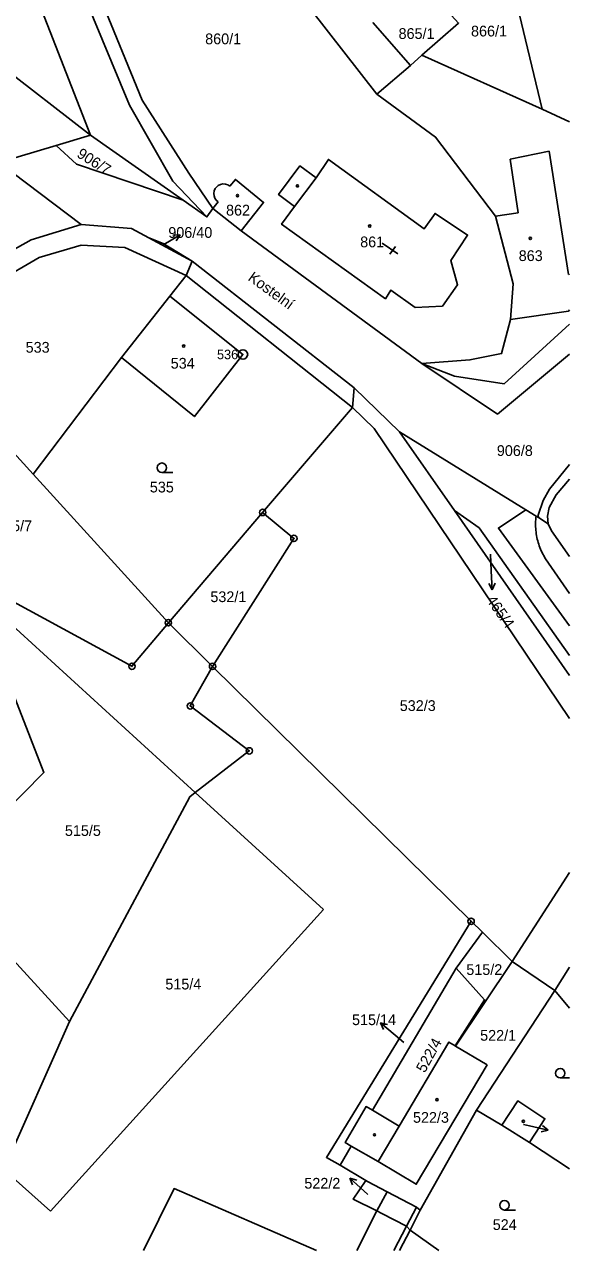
# Model space of a CAD drawing. Extents: x -776606 to -776076, y -974328 to -973875.
# Drawn here: x -776161.7 to -776075.5, y -974327.7 to -974133.7 of the extents above; entities that cross this region are included whole.
import ezdxf

# ---------------------------------------------------------------- set-up
doc = ezdxf.new("R2010")
doc.units = 0
for name, color, linetype in [('Hranice parcel', 7, 'Continuous'), ('Parcelní čísla', 7, 'Continuous'), ('Pop  PČ popisy', 7, 'Continuous'), ('Vnitřní kresba', 7, 'Continuous'), ('Značky bodu BP', 7, 'Continuous'), ('Značky budov', 7, 'Continuous'), ('Značky kultur', 7, 'Continuous')]:
    doc.layers.add(name, color=color, linetype=linetype)

msp = doc.modelspace()

# ---------------------------------------------------------------- linework, layer by layer
at = {"layer": 'Hranice parcel'}
for p, q in [((-776079.84, -974147.11), (-776087.39, -974115.46)), ((-776151.23, -974151.21), (-776174.9, -974132.93)), ((-776079.84, -974147.11), (-776098.85, -974138.57)), ((-776075.52, -974149.12), (-776079.84, -974147.11)), ((-776156.67, -974152.84), (-776151.23, -974151.21)), ((-776136.62, -974161.48), (-776151.23, -974151.21)), ((-776165.74, -974155.55), (-776156.67, -974152.84)), ((-776165.74, -974155.55), (-776152.75, -974165.36)), ((-776131.07, -974161.76), (-776131.92, -974162.82)), ((-776131.92, -974162.82), (-776127.42, -974166.36)), ((-776142.03, -974167.44), (-776139.75, -974168.37)), ((-776135.17, -974171.14), (-776142.03, -974167.44)), ((-776098.84, -974187.33), (-776127.42, -974166.36)), ((-776139.75, -974168.37), (-776135.17, -974171.14)), ((-776109.57, -974191.21), (-776135.17, -974171.14)), ((-776146.33, -974186.41), (-776138.73, -974176.69)), ((-776160.31, -974204.85), (-776146.33, -974186.41)), ((-776086.91, -974195.36), (-776075.52, -974185.86)), ((-776098.84, -974187.33), (-776086.91, -974195.36)), ((-776102.37, -974198.16), (-776109.57, -974191.21)), ((-776102.37, -974198.16), (-776093.72, -974210.57)), ((-776082.42, -974210.48), (-776102.37, -974198.16)), ((-776160.31, -974204.85), (-776138.94, -974228.35)), ((-776138.94, -974228.35), (-776124.04, -974210.91)), ((-776093.72, -974210.57), (-776075.52, -974236.68)), ((-776078.86, -974212.68), (-776080.43, -974211.71)), ((-776138.94, -974228.35), (-776144.7, -974235.24)), ((-776131.96, -974235.26), (-776138.94, -974228.35)), ((-776091.07, -974275.58), (-776131.96, -974235.26)), ((-776091.07, -974275.58), (-776089.29, -974277.33)), ((-776089.29, -974277.33), (-776093.45, -974283.01)), ((-776084.59, -974281.96), (-776089.29, -974277.33)), ((-776093.52, -974295.32), (-776084.59, -974281.96)), ((-776077.85, -974286.53), (-776084.59, -974281.96)), ((-776106.68, -974305.49), (-776093.45, -974283.01)), ((-776090.23, -974305.46), (-776077.85, -974286.53)), ((-776077.85, -974286.53), (-776075.52, -974289.31)), ((-776093.61, -974295.27), (-776093.52, -974295.32)), ((-776093.52, -974295.32), (-776088.52, -974298.29)), ((-776099.1, -974321.26), (-776090.23, -974305.46)), ((-776086.2, -974307.85), (-776090.23, -974305.46)), ((-776081.86, -974310.6), (-776086.2, -974307.85)), ((-776110.02, -974311.15), (-776111.8, -974314.18)), ((-776075.52, -974314.73), (-776081.86, -974310.6)), ((-776111.8, -974314.18), (-776107.73, -974316.58)), ((-776107.73, -974316.58), (-776107.43, -974316.76)), ((-776106, -974321.4), (-776109.16, -974327.66)), ((-776100.73, -974324.46), (-776099.1, -974321.26)), ((-776100.73, -974324.46), (-776102.39, -974327.66)), ((-776100.73, -974324.46), (-776101.29, -974323.83))]:
    msp.add_line(p, q, dxfattribs=at)
for points in [[(-776121.33, -974125.02), (-776116.42, -974131.34), (-776106, -974144.74)], [(-776098.85, -974138.57), (-776093.06, -974133.49), (-776098.09, -974127.94)], [(-776098.85, -974138.57), (-776100.67, -974140.17), (-776106, -974144.74)], [(-776106, -974144.74), (-776096.69, -974151.51), (-776087.2, -974164.02), (-776084.4, -974174.72), (-776084.85, -974180.38)], [(-776156.67, -974152.84), (-776153.49, -974155.81), (-776136.62, -974161.48)], [(-776118.97, -974162.5), (-776121.05, -974165.3), (-776104.61, -974177.1), (-776103.75, -974175.72), (-776099.89, -974178.5), (-776095.6, -974178.28), (-776093.22, -974174.87), (-776094.3, -974171.05), (-776091.62, -974167.01), (-776096.76, -974163.6), (-776098.49, -974166.02), (-776113.62, -974155.05), (-776115.59, -974157.96), (-776118.13, -974156.07), (-776121.51, -974160.61), (-776118.97, -974162.5)], [(-776129.22, -974159.3), (-776129.55, -974159.09), (-776129.92, -974158.97), (-776130.32, -974158.94), (-776130.7, -974159.02), (-776131.05, -974159.19), (-776131.27, -974159.37), (-776131.52, -974159.67), (-776131.68, -974160.03), (-776131.75, -974160.42), (-776131.72, -974160.81), (-776131.58, -974161.18), (-776131.36, -974161.5), (-776131.07, -974161.76)], [(-776127.42, -974166.36), (-776123.89, -974161.86), (-776128.33, -974158.21), (-776129.22, -974159.3)], [(-776131.92, -974162.82), (-776132.84, -974164.14), (-776136.62, -974161.48)], [(-776152.75, -974165.36), (-776160.65, -974167.77), (-776179.49, -974178.31), (-776182.59, -974180.14)], [(-776142.03, -974167.44), (-776144.77, -974165.96), (-776152.75, -974165.36)], [(-776138.73, -974176.69), (-776136.12, -974173.44), (-776135.17, -974171.14)], [(-776146.33, -974186.41), (-776134.81, -974195.73), (-776127.15, -974185.91), (-776138.73, -974176.69)], [(-776084.85, -974180.38), (-776075.69, -974179.07), (-776075.52, -974178.9)], [(-776182.59, -974180.14), (-776181.18, -974181.75), (-776178.4, -974184.94), (-776160.31, -974204.85)], [(-776084.85, -974180.38), (-776086.26, -974185.77), (-776091.27, -974186.78), (-776098.84, -974187.33)], [(-776098.84, -974187.33), (-776093.72, -974189.36), (-776085.86, -974190.55), (-776075.52, -974181.11)], [(-776187.91, -974186.49), (-776189.94, -974190.42), (-776197.63, -974205.37), (-776203.53, -974219.04), (-776202.03, -974219.5), (-776167.14, -974230.3), (-776158.63, -974252.03), (-776175.21, -974268.87), (-776154.58, -974291.43)], [(-776144.7, -974235.24), (-776164.02, -974224.74), (-776186.48, -974188.78), (-776187.91, -974186.49)], [(-776124.04, -974210.91), (-776109.85, -974194.3), (-776109.57, -974191.21)], [(-776080.43, -974211.71), (-776080.44, -974211.32), (-776079.69, -974209), (-776078.68, -974207.23), (-776075.52, -974203.34)], [(-776075.52, -974205.65), (-776077.62, -974208.13), (-776078.72, -974210.13), (-776078.98, -974211.47), (-776078.86, -974212.68)], [(-776075.52, -974228.83), (-776086.75, -974213.37), (-776082.42, -974210.48)], [(-776080.43, -974211.71), (-776080.8, -974211.48), (-776082.42, -974210.48)], [(-776124.04, -974210.91), (-776119.09, -974215), (-776131.96, -974235.26)], [(-776093.72, -974210.57), (-776089.82, -974213.33), (-776075.52, -974233.56)], [(-776078.86, -974212.68), (-776078.38, -974213.82), (-776075.52, -974217.88)], [(-776131.96, -974235.26), (-776135.48, -974241.52), (-776126.15, -974248.62), (-776134.68, -974255.2), (-776135.57, -974255.89), (-776154.58, -974291.43)], [(-776075.52, -974267.85), (-776084.59, -974281.96)], [(-776111.8, -974314.18), (-776113.96, -974312.94), (-776091.07, -974275.58)], [(-776093.45, -974283.01), (-776088.93, -974288), (-776093.61, -974295.27)], [(-776075.52, -974282.82), (-776077.85, -974286.53)], [(-776154.58, -974291.43), (-776164.96, -974314.87), (-776168.27, -974322.35)], [(-776093.61, -974295.27), (-776094.59, -974294.69), (-776102.46, -974307.99), (-776106.68, -974305.49)], [(-776088.52, -974298.29), (-776099.73, -974317.18), (-776105.78, -974313.61), (-776110.02, -974311.15)], [(-776110.02, -974311.15), (-776111, -974310.58), (-776107.67, -974304.9), (-776106.68, -974305.49)], [(-776081.86, -974310.6), (-776081.78, -974310.48), (-776079.41, -974306.81), (-776083.7, -974304), (-776086.2, -974307.85)], [(-776107.73, -974316.58), (-776109.71, -974319.55), (-776106, -974321.4)], [(-776107.43, -974316.76), (-776104.34, -974318.39), (-776099.72, -974320.81), (-776099.1, -974321.26)], [(-776115.51, -974327.66), (-776138.03, -974317.86), (-776142.89, -974327.66)], [(-776101.29, -974323.83), (-776105.17, -974321.83), (-776106, -974321.4)], [(-776101.29, -974323.83), (-776103.28, -974327.66)], [(-776096.18, -974327.66), (-776100.73, -974324.46)]]:
    msp.add_lwpolyline(points, dxfattribs=at)
at = {"layer": 'Pop  PČ popisy'}
for p, q in [((-776139.67, -974168.52), (-776137.1, -974166.97)), ((-776137.1, -974166.97), (-776138.21, -974167.06)), ((-776137.1, -974166.97), (-776137.7, -974167.92)), ((-776139.74, -974168.56), (-776139.67, -974168.52)), ((-776088, -974217.51), (-776087.88, -974220.13)), ((-776087.88, -974220.13), (-776087.72, -974223.13)), ((-776087.72, -974223.13), (-776087.28, -974222.1)), ((-776087.72, -974223.13), (-776088.28, -974222.15)), ((-776103.09, -974293.59), (-776105.39, -974291.66)), ((-776105.39, -974291.66), (-776104.3, -974291.92)), ((-776105.39, -974291.66), (-776104.94, -974292.69)), ((-776101.72, -974294.75), (-776103.09, -974293.59)), ((-776082.8, -974307.72), (-776081.82, -974307.94)), ((-776081.82, -974307.94), (-776078.9, -974308.61)), ((-776078.9, -974308.61), (-776079.98, -974308.88)), ((-776078.9, -974308.61), (-776079.76, -974307.9)), ((-776108.01, -974318.24), (-776110.24, -974316.23)), ((-776110.24, -974316.23), (-776109.16, -974316.53)), ((-776110.24, -974316.23), (-776109.83, -974317.27)), ((-776107.38, -974318.81), (-776108.01, -974318.24))]:
    msp.add_line(p, q, dxfattribs=at)
at = {"layer": 'Vnitřní kresba'}
for p, q in [((-776145.11, -974146.49), (-776153.97, -974124.96)), ((-776151.91, -974124.13), (-776143.06, -974145.68)), ((-776161.1, -974126), (-776151.23, -974151.21)), ((-776106.63, -974133.38), (-776100.67, -974140.17)), ((-776138.21, -974158.48), (-776145.11, -974146.49)), ((-776143.06, -974145.68), (-776135.72, -974157.25)), ((-776084.87, -974155.01), (-776078.72, -974153.74)), ((-776078.72, -974153.74), (-776075.69, -974173.24)), ((-776083.65, -974163.51), (-776084.87, -974155.01)), ((-776135.72, -974157.25), (-776131.92, -974162.82)), ((-776115.59, -974157.96), (-776118.97, -974162.5)), ((-776132.84, -974164.14), (-776138.21, -974158.48)), ((-776087.2, -974164.02), (-776083.65, -974163.51)), ((-776152.75, -974168.63), (-776159.38, -974170.55)), ((-776145.84, -974168.99), (-776152.75, -974168.63)), ((-776136.12, -974173.44), (-776145.84, -974168.99)), ((-776159.38, -974170.55), (-776177.61, -974181.19)), ((-776136.12, -974173.44), (-776109.85, -974194.3)), ((-776075.69, -974173.24), (-776075.52, -974173.21)), ((-776075.52, -974178.84), (-776075.69, -974179.07)), ((-776106.41, -974197.64), (-776109.85, -974194.3)), ((-776075.52, -974243.49), (-776106.41, -974197.64)), ((-776189.23, -974205.43), (-776134.68, -974255.2)), ((-776075.52, -974223.73), (-776079.3, -974218.23)), ((-776134.68, -974255.2), (-776114.4, -974273.7)), ((-776114.4, -974273.7), (-776157.6, -974321.47)), ((-776102.46, -974307.99), (-776105.78, -974313.61)), ((-776157.6, -974321.47), (-776164.96, -974314.87)), ((-776104.34, -974318.39), (-776106, -974321.4)), ((-776101.29, -974323.83), (-776099.72, -974320.81))]:
    msp.add_line(p, q, dxfattribs=at)
msp.add_lwpolyline([(-776079.3, -974218.23), (-776079.45, -974217.99), (-776079.59, -974217.74), (-776079.72, -974217.5), (-776079.85, -974217.24), (-776079.97, -974216.99), (-776080.08, -974216.73), (-776080.19, -974216.47), (-776080.29, -974216.2), (-776080.38, -974215.94), (-776080.46, -974215.67), (-776080.54, -974215.4), (-776080.6, -974215.12), (-776080.67, -974214.85), (-776080.72, -974214.57), (-776080.77, -974214.29), (-776080.8, -974214.01), (-776080.83, -974213.73), (-776080.86, -974213.45), (-776080.87, -974213.17), (-776080.88, -974212.89), (-776080.88, -974212.6), (-776080.87, -974212.32), (-776080.85, -974212.04), (-776080.83, -974211.76), (-776080.8, -974211.48)], dxfattribs=at)
at = {"layer": 'Značky bodu BP'}
for centre, radius in [((-776127.15, -974185.91), 0.75), ((-776127.15, -974185.91), 0.03), ((-776124.04, -974210.91), 0.5), ((-776124.04, -974210.91), 0.0303), ((-776119.09, -974215), 0.5), ((-776119.09, -974215), 0.0303), ((-776138.94, -974228.35), 0.5), ((-776138.94, -974228.35), 0.0303), ((-776144.7, -974235.24), 0.5), ((-776144.7, -974235.24), 0.0303), ((-776131.96, -974235.26), 0.5), ((-776131.96, -974235.26), 0.0303), ((-776135.48, -974241.52), 0.5), ((-776135.48, -974241.52), 0.0303), ((-776126.15, -974248.62), 0.5), ((-776126.15, -974248.62), 0.0303), ((-776091.07, -974275.58), 0.5), ((-776091.07, -974275.58), 0.0303)]:
    msp.add_circle(centre, radius, dxfattribs=at)
at = {"layer": 'Značky budov'}
for p, q in [((-776102.65, -974170.01), (-776105.11, -974168.29)), ((-776103.04, -974168.82), (-776103.9, -974170.05))]:
    msp.add_line(p, q, dxfattribs=at)
for centre in [(-776118.53, -974159.24), (-776128.01, -974160.77), (-776107.1, -974165.6), (-776081.71, -974167.55), (-776136.52, -974184.58), (-776096.46, -974303.82), (-776082.81, -974307.22), (-776106.35, -974309.37)]:
    msp.add_circle(centre, 0.175, dxfattribs=at)
at = {"layer": 'Značky kultur'}
for p, q in [((-776139.96, -974204.58), (-776138.21, -974204.58)), ((-776076.98, -974300.37), (-776075.52, -974300.37)), ((-776085.8, -974321.26), (-776084.05, -974321.26))]:
    msp.add_line(p, q, dxfattribs=at)
for centre in [(-776139.96, -974203.83), (-776076.98, -974299.62), (-776085.8, -974320.51)]:
    msp.add_circle(centre, 0.75, dxfattribs=at)

# ---------------------------------------------------------------- texts
at = {"layer": 'Parcelní čísla'}
for s, p in [('865/1', (-776102.54, -974135.99)), ('866/1', (-776091.08, -974135.6)), ('860/1', (-776133.12, -974136.83)), ('862', (-776129.82, -974163.93)), ('906/40', (-776138.95, -974167.46)), ('861', (-776108.61, -974168.95)), ('863', (-776083.54, -974171.13)), ('533', (-776161.51, -974185.63)), ('534', (-776138.57, -974188.15)), ('906/8', (-776087, -974201.97)), ('535', (-776141.87, -974207.74)), ('515/7', (-776166.18, -974213.87)), ('532/1', (-776132.3, -974225.09)), ('532/3', (-776102.35, -974242.31)), ('515/5', (-776155.3, -974262.08)), ('515/2', (-776091.83, -974284.08)), ('515/4', (-776139.42, -974286.37)), ('515/14', (-776109.9, -974292.01)), ('522/1', (-776089.64, -974294.48)), ('522/3', (-776100.26, -974307.46)), ('522/2', (-776117.44, -974317.88)), ('524', (-776087.65, -974324.42))]:
    msp.add_text(s, height=1.7, dxfattribs=at).set_placement(p)
for s, rotation, p in [('906/7', 328, (-776153.54, -974154.58)), ('465/4', 305, (-776088.76, -974224.76)), ('522/4', 61, (-776098.39, -974299.66))]:
    msp.add_text(s, height=1.7, rotation=rotation, dxfattribs=at).set_placement(p)
at = {"layer": 'Pop  PČ popisy'}
msp.add_text('Kostelní', height=1.7, rotation=324, dxfattribs=at).set_placement((-776126.48, -974174.07))
at = {"layer": 'Značky bodu BP'}
msp.add_text('536', height=1.5, dxfattribs=at).set_placement((-776131.25, -974186.66))

doc.saveas('drawing.dxf')
